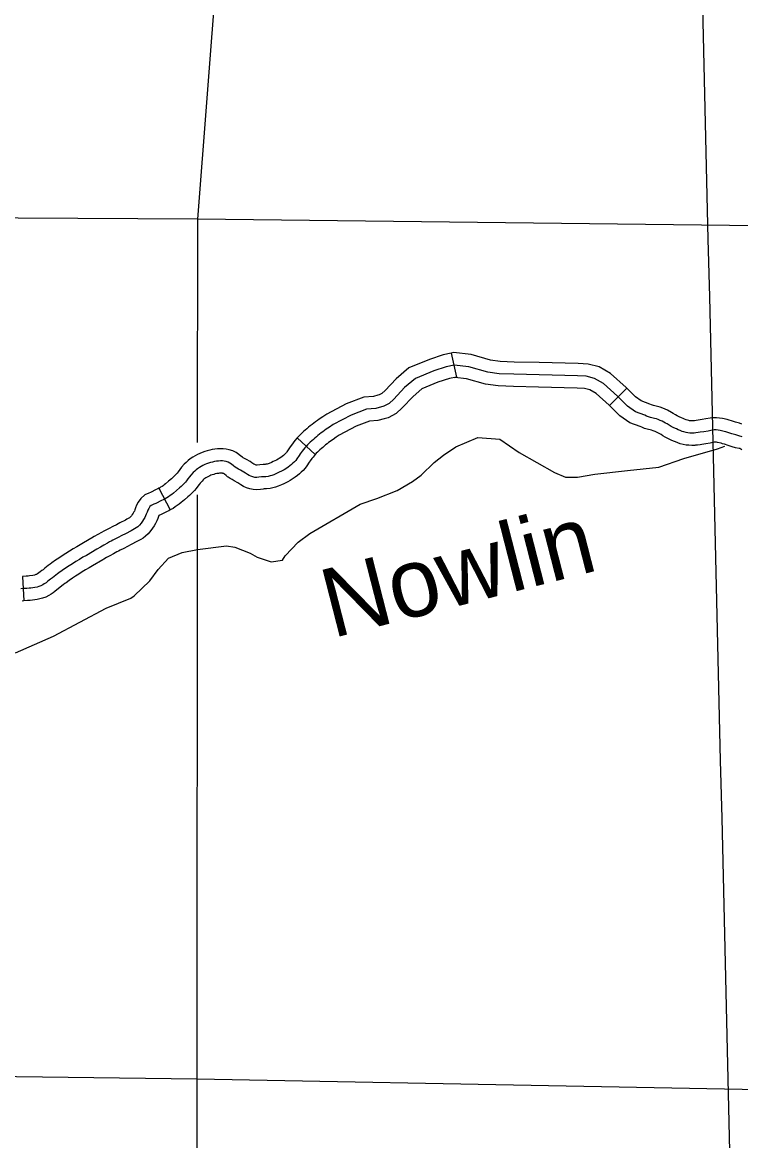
# Model space of a CAD drawing. Extents: x -19 to 366, y -4 to 359.
# Drawn here: x 134.181 to 135.016, y 195.99 to 197.29 of the extents above; entities that cross this region are included whole.
import ezdxf

# ---------------------------------------------------------------- set-up
doc = ezdxf.new("R2010")
doc.units = 0
for name, color, linetype in [('R_Axis Annot', 7, 'Continuous'), ('R_Temp Easement', 7, 'Continuous'), ('Sheet Fence', 7, 'Continuous'), ('T_Indications', 7, 'Continuous')]:
    doc.layers.add(name, color=color, linetype=linetype)

msp = doc.modelspace()

# ---------------------------------------------------------------- linework, layer by layer
at = {"layer": 'R_Axis Annot'}
for points in [[(134.4615, 198.0663), (134.3841, 197.0611)], [(134.3841, 197.0611), (133.6196, 197.0653)], [(134.3841, 197.0611), (134.3839, 196.8016)], [(135.3933, 197.049), (134.3841, 197.0611)], [(134.3839, 196.7408), (134.3834, 196.0617)], [(133.4555, 196.0738), (134.3834, 196.0617)], [(134.3834, 196.0617), (135.2832, 196.0448)], [(134.3834, 196.0617), (134.3847, 195.4655)]]:
    msp.add_lwpolyline(points, dxfattribs=at)
at = {"layer": 'R_Temp Easement'}
for points in [[(134.5928, 196.7366), (134.6162, 196.7459), (134.6339, 196.7564), (134.644, 196.7637), (134.6594, 196.7782), (134.6702, 196.7867), (134.6845, 196.7967), (134.7101, 196.8075), (134.7355, 196.8055), (134.7579, 196.7898), (134.799, 196.7667), (134.8119, 196.7611), (134.8259, 196.7613), (134.8459, 196.7649), (134.884, 196.769), (134.9206, 196.7728), (134.9493, 196.7829), (134.9885, 196.7943)], [(134.9885, 196.7943), (134.9973, 196.7973)], [(134.1726, 196.557), (134.2167, 196.5764), (134.278, 196.6088), (134.3066, 196.6208), (134.3104, 196.6232), (134.3287, 196.6408), (134.3384, 196.6538), (134.3504, 196.6671), (134.3662, 196.6737), (134.3843, 196.6773), (134.4179, 196.6815), (134.4274, 196.68), (134.4452, 196.673), (134.4536, 196.6682), (134.4699, 196.663), (134.4831, 196.6647), (134.4861, 196.67), (134.5011, 196.6857), (134.5146, 196.6957), (134.5732, 196.73), (134.5928, 196.7366)]]:
    msp.add_lwpolyline(points, dxfattribs=at)
at = {"layer": 'Sheet Fence'}
for points in [[(139.4406, 1.5315), (139.2511, 10.1473), (139.0608, 18.7633), (138.8699, 27.3793), (138.6784, 35.9956), (138.4861, 44.6119), (138.2932, 53.2285), (138.0997, 61.8451), (137.9055, 70.4619), (137.7106, 79.0789), (137.5151, 87.6959), (137.319, 96.3132), (137.1221, 104.9306), (136.9247, 113.5481), (136.7265, 122.1658), (136.5278, 130.7836), (136.3283, 139.4016), (136.1282, 148.0197), (135.9275, 156.6379), (135.7261, 165.2564), (135.5241, 173.8749), (135.3214, 182.4936), (135.1181, 191.1125), (134.9141, 199.7315), (134.7095, 208.3506), (134.5043, 216.9699), (134.2984, 225.5894), (134.0919, 234.209), (133.8847, 242.8288), (133.6769, 251.4487), (133.4685, 260.0687), (133.2594, 268.6889), (133.0497, 277.3093), (132.8393, 285.9298), (132.6283, 294.5504), (132.4167, 303.1713), (132.2044, 311.7922), (131.9916, 320.4133), (131.778, 329.0346), (131.5639, 337.656), (131.3491, 346.2776)], [(0, 189.5162), (7.1121, 189.5206), (14.2243, 189.5339), (21.3364, 189.556), (28.4484, 189.5869), (35.5605, 189.6267), (42.6725, 189.6754), (49.7844, 189.7329), (56.8962, 189.7992), (64.0079, 189.8744), (71.1196, 189.9584), (78.2311, 190.0512), (85.3425, 190.1529), (92.4538, 190.2635), (99.5649, 190.3829), (106.6759, 190.5111), (113.7867, 190.6482), (120.8974, 190.7941), (128.0078, 190.9489), (135.1181, 191.1125), (142.2282, 191.2849), (149.338, 191.4662), (156.4476, 191.6563), (163.5569, 191.8553), (170.666, 192.0631), (177.7749, 192.2798), (184.8835, 192.5053), (191.9917, 192.7396), (199.0997, 192.9828), (206.2074, 193.2348), (213.3147, 193.4956), (220.4218, 193.7653), (227.5285, 194.0438), (234.6348, 194.3312), (241.7408, 194.6274), (248.8464, 194.9324), (255.9516, 195.2463), (263.0564, 195.569), (270.1608, 195.9005), (277.2648, 196.2409), (284.3683, 196.5901), (291.4715, 196.9481), (298.5741, 197.315), (305.6763, 197.6907), (312.7781, 198.0753), (319.8793, 198.4686), (326.9801, 198.8708), (334.0804, 199.2818), (341.1801, 199.7017)]]:
    msp.add_spline(points, degree=3, dxfattribs=at)
at = {"layer": 'T_Indications'}
for p, q in [((134.6792, 196.9054), (134.6851, 196.8776)), ((134.8831, 196.8647), (134.863, 196.8446)), ((134.5002, 196.807), (134.5211, 196.7878)), ((134.3392, 196.7483), (134.3524, 196.7232)), ((134.1806, 196.6459), (134.1822, 196.6175))]:
    msp.add_line(p, q, dxfattribs=at)
for points in [[(134.6792, 196.9054), (134.6696, 196.9034), (134.6538, 196.8982), (134.63, 196.8884), (134.615, 196.8757), (134.6022, 196.862), (134.5986, 196.8587), (134.5953, 196.8569), (134.5939, 196.8565)], [(134.7814, 196.8944), (134.7522, 196.8951), (134.7361, 196.8956), (134.7247, 196.8973), (134.7022, 196.9037), (134.6818, 196.906), (134.6792, 196.9054)], [(134.9043, 196.8332), (134.8933, 196.8373), (134.8841, 196.8436), (134.8724, 196.8553), (134.856, 196.8703), (134.8458, 196.8761), (134.8361, 196.8785), (134.8259, 196.879), (134.7518, 196.8809), (134.7348, 196.8814), (134.7217, 196.8834), (134.6994, 196.8897), (134.6825, 196.8916), (134.6733, 196.8897), (134.6587, 196.8848), (134.6374, 196.8761), (134.6248, 196.8654), (134.6122, 196.8519), (134.6069, 196.847), (134.6006, 196.8436), (134.5914, 196.8412), (134.5807, 196.8402), (134.5628, 196.8334), (134.5418, 196.8223)], [(134.8831, 196.8647), (134.8823, 196.8655), (134.8644, 196.8818), (134.8511, 196.8894), (134.8382, 196.8926), (134.8265, 196.8932), (134.7814, 196.8944)], [(134.6851, 196.8776), (134.677, 196.8759), (134.6637, 196.8715), (134.6449, 196.8638), (134.6347, 196.8551), (134.6222, 196.8418), (134.6152, 196.8353), (134.6058, 196.8303), (134.6011, 196.8291)], [(134.7806, 196.866), (134.7514, 196.8668), (134.7336, 196.8673), (134.7188, 196.8695), (134.6967, 196.8757), (134.6832, 196.8772), (134.6851, 196.8776)], [(134.863, 196.8446), (134.8626, 196.845), (134.8476, 196.8587), (134.8404, 196.8628), (134.834, 196.8644), (134.8254, 196.8648), (134.7806, 196.866)], [(134.5939, 196.8565), (134.5889, 196.8552), (134.5775, 196.8542), (134.5569, 196.8464), (134.5345, 196.8345), (134.5297, 196.8313), (134.5256, 196.8286), (134.5235, 196.8271), (134.5215, 196.8256), (134.5193, 196.8241), (134.5173, 196.8225), (134.5153, 196.8209), (134.5133, 196.8192), (134.5112, 196.8175), (134.5094, 196.8159), (134.5074, 196.8142), (134.5055, 196.8124), (134.5035, 196.8104), (134.5016, 196.8085), (134.5002, 196.807)], [(134.9606, 196.8266), (134.9591, 196.8266), (134.9572, 196.8267), (134.9561, 196.8268), (134.9552, 196.827), (134.9538, 196.8274), (134.9522, 196.8279), (134.9504, 196.8286), (134.9486, 196.8293), (134.9466, 196.8302), (134.9442, 196.8313), (134.9418, 196.8326), (134.9398, 196.8338), (134.9372, 196.8354), (134.935, 196.8366), (134.9305, 196.839), (134.9277, 196.8403), (134.9249, 196.8415), (134.9219, 196.8425), (134.9188, 196.8433), (134.9144, 196.8444), (134.9129, 196.8448), (134.912, 196.8452), (134.9099, 196.8462), (134.8999, 196.85), (134.8932, 196.8546), (134.8831, 196.8647)], [(134.9629, 196.7983), (134.9621, 196.7982), (134.9586, 196.7982), (134.9553, 196.7983), (134.9522, 196.7986), (134.9488, 196.7992), (134.9453, 196.8002), (134.9426, 196.8012), (134.9399, 196.8022), (134.9375, 196.8032), (134.9349, 196.8043), (134.9315, 196.8059), (134.9277, 196.8079), (134.925, 196.8095), (134.923, 196.8107), (134.9216, 196.8115), (134.9178, 196.8136), (134.916, 196.8144), (134.9148, 196.8149), (134.9137, 196.8153), (134.9118, 196.8158), (134.907, 196.8169), (134.9037, 196.8179), (134.9005, 196.8192), (134.8986, 196.8201), (134.8867, 196.8246), (134.875, 196.8326), (134.863, 196.8446)], [(134.6011, 196.8291), (134.5939, 196.8272), (134.5839, 196.8263), (134.5687, 196.8205), (134.549, 196.81), (134.5455, 196.8077), (134.5417, 196.8051), (134.5399, 196.8039), (134.5382, 196.8026), (134.5365, 196.8014), (134.5348, 196.8001), (134.5331, 196.7988), (134.5315, 196.7974), (134.5297, 196.7959), (134.5281, 196.7945), (134.5264, 196.7931), (134.525, 196.7918), (134.5235, 196.7903), (134.5222, 196.789), (134.5211, 196.7878)], [(135.0174, 196.8083), (135.0133, 196.8093), (135.0098, 196.8103), (135.0053, 196.8117), (135.0008, 196.8131), (134.9984, 196.8138), (134.9962, 196.8144), (134.9916, 196.8155), (134.9893, 196.8159), (134.9869, 196.8161), (134.9846, 196.8161), (134.9823, 196.8158), (134.9776, 196.8149), (134.9729, 196.8141), (134.9683, 196.8134), (134.9662, 196.8131), (134.9636, 196.8127), (134.9613, 196.8124), (134.9589, 196.8124), (134.9563, 196.8125), (134.9541, 196.8127), (134.952, 196.8131), (134.9496, 196.8138), (134.9474, 196.8145), (134.9451, 196.8154), (134.943, 196.8163), (134.9408, 196.8173), (134.9378, 196.8186), (134.9348, 196.8202), (134.9324, 196.8217), (134.9301, 196.8231), (134.9283, 196.8241), (134.9241, 196.8263), (134.9218, 196.8273), (134.9198, 196.8282), (134.9178, 196.8289), (134.9153, 196.8296), (134.9107, 196.8307), (134.9083, 196.8314), (134.9062, 196.8322), (134.9043, 196.8332)], [(135.017, 196.823), (135.014, 196.8239), (135.0095, 196.8253), (135.0049, 196.8267), (135.0023, 196.8275), (134.9998, 196.8282), (134.9944, 196.8295), (134.991, 196.83), (134.9876, 196.8303), (134.9836, 196.8303), (134.9799, 196.8298), (134.9751, 196.8289), (134.9707, 196.8281), (134.9661, 196.8274), (134.964, 196.8271), (134.9617, 196.8267), (134.96, 196.8266)], [(134.5418, 196.8223), (134.5376, 196.8195), (134.5337, 196.8169), (134.5317, 196.8155), (134.5298, 196.8141), (134.5279, 196.8127), (134.526, 196.8113), (134.5242, 196.8098), (134.5224, 196.8083), (134.5204, 196.8067), (134.5188, 196.8052), (134.5169, 196.8036), (134.5152, 196.8021), (134.5135, 196.8004), (134.5119, 196.7987), (134.5104, 196.7971), (134.5088, 196.7952), (134.5074, 196.7935), (134.5058, 196.7915), (134.5035, 196.7884), (134.5022, 196.7864), (134.4997, 196.7826), (134.4983, 196.7808), (134.4968, 196.7791), (134.4951, 196.7775), (134.4933, 196.7759), (134.4915, 196.7744), (134.4894, 196.7728), (134.4867, 196.7709), (134.4848, 196.7698), (134.4826, 196.7686), (134.4783, 196.7665), (134.4761, 196.7654), (134.4727, 196.764), (134.4706, 196.7633), (134.4685, 196.7627), (134.4662, 196.7622), (134.4636, 196.7618), (134.4612, 196.7618), (134.4587, 196.7616), (134.4555, 196.7611), (134.453, 196.7608), (134.4508, 196.761), (134.4486, 196.7615), (134.4462, 196.7623), (134.4442, 196.7632), (134.4421, 196.7645), (134.4398, 196.766), (134.4381, 196.767), (134.434, 196.7693), (134.4317, 196.7706), (134.4299, 196.7717), (134.428, 196.7729), (134.426, 196.7745), (134.4238, 196.7762), (134.4217, 196.7776), (134.4197, 196.7787), (134.4174, 196.7795), (134.4153, 196.7799), (134.4133, 196.7801), (134.411, 196.7801), (134.4086, 196.78), (134.4064, 196.7797), (134.4039, 196.7793), (134.4015, 196.7788), (134.3993, 196.7783), (134.397, 196.7776), (134.3947, 196.7768), (134.3926, 196.7759), (134.3904, 196.7749), (134.3884, 196.7738), (134.3863, 196.7725), (134.3841, 196.771), (134.3825, 196.7698), (134.3809, 196.7683), (134.3791, 196.7665), (134.3765, 196.7636), (134.3748, 196.7615), (134.3731, 196.7592), (134.3715, 196.757), (134.3701, 196.7555), (134.3686, 196.7538), (134.3668, 196.7521), (134.3652, 196.7506), (134.3633, 196.7489), (134.3598, 196.7458), (134.3562, 196.7427), (134.3542, 196.7411), (134.3524, 196.7398), (134.3506, 196.7385), (134.3485, 196.7372), (134.3465, 196.7361), (134.3443, 196.735), (134.3425, 196.734), (134.3358, 196.7308), (134.3334, 196.7297), (134.3304, 196.7284), (134.3288, 196.727), (134.3274, 196.725), (134.3263, 196.7228)], [(134.5002, 196.807), (134.4997, 196.8065), (134.4978, 196.8042), (134.4962, 196.8023), (134.4945, 196.8001), (134.492, 196.7967), (134.4903, 196.7942), (134.488, 196.7907), (134.4875, 196.79), (134.4867, 196.7891), (134.4854, 196.7878), (134.484, 196.7866), (134.4826, 196.7854), (134.481, 196.7842), (134.4791, 196.7829), (134.4779, 196.7822), (134.4761, 196.7812), (134.4722, 196.7793), (134.4703, 196.7784), (134.4676, 196.7773), (134.4662, 196.7768), (134.465, 196.7765), (134.4637, 196.7762), (134.4627, 196.776), (134.4605, 196.776), (134.4568, 196.7757), (134.4537, 196.7752), (134.453, 196.7751), (134.4525, 196.7752), (134.4514, 196.7756), (134.4508, 196.7758), (134.4497, 196.7765), (134.4474, 196.778), (134.4452, 196.7793), (134.441, 196.7817), (134.4389, 196.7829), (134.4374, 196.7838), (134.4363, 196.7845), (134.4364, 196.7844)], [(135.0167, 196.7932), (135.0144, 196.7944), (135.0137, 196.7946), (135.0096, 196.7955), (135.0056, 196.7967), (135.0011, 196.7982), (134.9967, 196.7995), (134.9945, 196.8002), (134.9927, 196.8007), (134.9888, 196.8016), (134.9875, 196.8018), (134.9863, 196.8019), (134.9855, 196.8019), (134.9846, 196.8018), (134.9801, 196.8009), (134.9752, 196.8001), (134.9704, 196.7993), (134.9684, 196.799), (134.9655, 196.7986), (134.9629, 196.7983)], [(134.4364, 196.7844), (134.4347, 196.7857), (134.4322, 196.7877), (134.429, 196.7899), (134.4253, 196.7918), (134.4211, 196.7932), (134.4173, 196.794), (134.414, 196.7943), (134.4107, 196.7943), (134.4074, 196.7942), (134.4044, 196.7938), (134.4012, 196.7933), (134.3984, 196.7927), (134.3955, 196.792), (134.3926, 196.7911), (134.3897, 196.7901), (134.3868, 196.7889), (134.384, 196.7876), (134.3813, 196.7861), (134.3786, 196.7845), (134.3757, 196.7825), (134.3733, 196.7806), (134.371, 196.7785), (134.3688, 196.7763), (134.3657, 196.7728), (134.3635, 196.7701), (134.3617, 196.7676), (134.3604, 196.7659), (134.3596, 196.765), (134.3584, 196.7638), (134.357, 196.7623), (134.3556, 196.761), (134.3539, 196.7595), (134.3505, 196.7565), (134.3471, 196.7536), (134.3455, 196.7523), (134.3442, 196.7513), (134.3429, 196.7504), (134.3413, 196.7495), (134.3398, 196.7486), (134.3392, 196.7483)], [(134.5211, 196.7878), (134.521, 196.7876), (134.5197, 196.7862), (134.5186, 196.7847), (134.5171, 196.7829), (134.5151, 196.7801), (134.514, 196.7786), (134.5113, 196.7744), (134.5092, 196.7716), (134.5069, 196.7692), (134.5048, 196.7671), (134.5026, 196.7652), (134.5004, 196.7633), (134.4978, 196.7613), (134.4943, 196.7589), (134.4917, 196.7574), (134.489, 196.7559), (134.4845, 196.7537), (134.4818, 196.7524), (134.4779, 196.7508), (134.4749, 196.7497), (134.4719, 196.7489), (134.4686, 196.7482), (134.4645, 196.7476), (134.4618, 196.7476), (134.4605, 196.7475), (134.4573, 196.747), (134.4531, 196.7466), (134.4487, 196.7469), (134.4448, 196.7478), (134.4411, 196.749), (134.4377, 196.7506), (134.4345, 196.7525), (134.4323, 196.7539), (134.431, 196.7547), (134.4269, 196.757), (134.4245, 196.7584), (134.4223, 196.7597), (134.4198, 196.7613), (134.4192, 196.7618)], [(134.4192, 196.7618), (134.4173, 196.7632), (134.4154, 196.7648), (134.4144, 196.7654), (134.414, 196.7656), (134.4137, 196.7657), (134.4134, 196.7658), (134.4126, 196.7659), (134.4112, 196.7659), (134.4097, 196.7658), (134.4084, 196.7657), (134.4065, 196.7654), (134.4047, 196.765), (134.403, 196.7645), (134.4013, 196.764), (134.3998, 196.7635), (134.3984, 196.7629), (134.3969, 196.7622), (134.3954, 196.7614), (134.394, 196.7606), (134.3925, 196.7596), (134.3917, 196.7589), (134.3907, 196.758), (134.3894, 196.7567), (134.3872, 196.7543), (134.3861, 196.7529), (134.3845, 196.7507), (134.3826, 196.7481), (134.3807, 196.7459), (134.3787, 196.7438), (134.3767, 196.7419), (134.3748, 196.7401), (134.3728, 196.7383), (134.3691, 196.7351), (134.3653, 196.7318), (134.363, 196.7299), (134.3607, 196.7282), (134.3583, 196.7266), (134.3557, 196.725), (134.3533, 196.7236), (134.3524, 196.7232)], [(134.3392, 196.7483), (134.3379, 196.7476), (134.3362, 196.7468), (134.3297, 196.7436), (134.3276, 196.7426), (134.3228, 196.7406), (134.3181, 196.7365), (134.3151, 196.7322), (134.3133, 196.7286), (134.3122, 196.7257), (134.3113, 196.7233), (134.3108, 196.7219), (134.3102, 196.7209), (134.3093, 196.7193), (134.3084, 196.7179), (134.3075, 196.7165), (134.3063, 196.7151), (134.3058, 196.7146), (134.305, 196.7141), (134.3037, 196.7133), (134.302, 196.7123), (134.3004, 196.7114), (134.294, 196.7081), (134.2899, 196.706), (134.2857, 196.7039), (134.2814, 196.7017), (134.2791, 196.7005), (134.277, 196.6994), (134.2751, 196.6984), (134.2726, 196.6971), (134.2684, 196.6947), (134.2642, 196.6923), (134.2609, 196.6904)], [(134.3263, 196.7228), (134.3255, 196.7207), (134.3246, 196.7183), (134.3238, 196.7162), (134.3228, 196.7142), (134.3215, 196.712), (134.3202, 196.71), (134.3187, 196.7078), (134.3166, 196.7053), (134.3149, 196.7037), (134.313, 196.7023), (134.311, 196.7011), (134.3089, 196.6999), (134.3071, 196.6989), (134.3005, 196.6954), (134.2963, 196.6933), (134.2921, 196.6912), (134.2879, 196.6891), (134.2857, 196.6879), (134.2837, 196.6869), (134.2819, 196.6859), (134.2795, 196.6846), (134.2754, 196.6823), (134.2713, 196.68), (134.2672, 196.6776), (134.255, 196.6704), (134.2509, 196.6681), (134.2468, 196.6656), (134.2428, 196.6632), (134.2388, 196.6607), (134.2348, 196.6581), (134.2308, 196.6555), (134.2269, 196.6529), (134.2231, 196.6502), (134.2213, 196.6489), (134.2193, 196.6473), (134.2156, 196.6443), (134.2134, 196.6426), (134.2119, 196.6414), (134.2099, 196.6398), (134.2081, 196.6385), (134.2061, 196.6372), (134.2042, 196.636), (134.2022, 196.6349), (134.1999, 196.6341), (134.1978, 196.6335), (134.1952, 196.633), (134.1905, 196.6323), (134.1884, 196.6321), (134.1858, 196.6319), (134.1811, 196.6317), (134.1786, 196.6314)], [(134.3524, 196.7232), (134.3508, 196.7223), (134.3488, 196.7213), (134.3419, 196.718), (134.3392, 196.7167), (134.3391, 196.7167), (134.3388, 196.7157), (134.3379, 196.7133), (134.3368, 196.7104), (134.3353, 196.7075), (134.3337, 196.7046), (134.332, 196.702), (134.33, 196.6992), (134.3269, 196.6955), (134.3239, 196.6927), (134.3209, 196.6905), (134.3184, 196.6889), (134.3158, 196.6875), (134.3138, 196.6863), (134.307, 196.6828), (134.3027, 196.6806), (134.2985, 196.6785), (134.2943, 196.6764), (134.2922, 196.6753), (134.2903, 196.6743), (134.2886, 196.6734), (134.2864, 196.6722), (134.2824, 196.67), (134.2784, 196.6677), (134.2752, 196.6658)], [(134.2609, 196.6904), (134.2601, 196.6899), (134.2478, 196.6827), (134.2437, 196.6803), (134.2395, 196.6778), (134.2353, 196.6753), (134.2312, 196.6727), (134.227, 196.67), (134.2229, 196.6673), (134.2189, 196.6646), (134.2148, 196.6617), (134.2127, 196.6602), (134.2105, 196.6585), (134.2067, 196.6554), (134.2046, 196.6537), (134.2031, 196.6526), (134.2014, 196.6512), (134.1999, 196.6501), (134.1983, 196.649), (134.1971, 196.6483), (134.1964, 196.648), (134.1956, 196.6477), (134.1946, 196.6474), (134.1927, 196.647), (134.1888, 196.6464), (134.1873, 196.6463), (134.1849, 196.6461), (134.1806, 196.6459)], [(134.2752, 196.6658), (134.2743, 196.6653), (134.2621, 196.6582), (134.2581, 196.6558), (134.2541, 196.6535), (134.2502, 196.6511), (134.2464, 196.6487), (134.2425, 196.6462), (134.2387, 196.6437), (134.235, 196.6412), (134.2313, 196.6386), (134.2298, 196.6375), (134.2281, 196.6362), (134.2245, 196.6333), (134.2223, 196.6315), (134.2206, 196.6302), (134.2184, 196.6285), (134.2163, 196.6269), (134.2139, 196.6253), (134.2112, 196.6236), (134.2079, 196.6219), (134.2041, 196.6205), (134.201, 196.6197), (134.1977, 196.619), (134.1923, 196.6182), (134.1896, 196.6179), (134.1867, 196.6178), (134.1822, 196.6175)], [(134.1822, 196.6175), (134.1822, 196.6175), (134.1804, 196.6173)]]:
    msp.add_lwpolyline(points, dxfattribs=at)

# ---------------------------------------------------------------- texts
at = {"layer": 'R_Temp Easement'}
msp.add_text('Nowlin', height=0.08, rotation=14.3627, dxfattribs=at).set_placement((134.5409, 196.5739))

doc.saveas('drawing.dxf')
